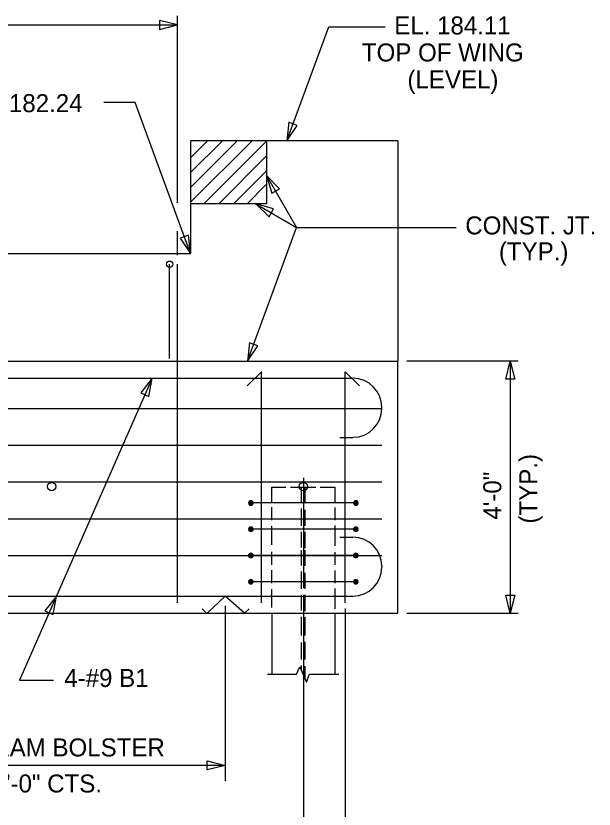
# Model space of a CAD drawing. Extents: x -41 to 251, y -169 to 237.
# Drawn here: x 46.48 to 55.67, y -39.68 to -27.08 of the extents above; entities that cross this region are included whole.
import ezdxf

# ---------------------------------------------------------------- set-up
doc = ezdxf.new("R2010")
doc.units = 0
for name, color, linetype in [('Arrowhead Terminators', 7, 'Continuous'), ('Arrowhead Terminators CELL', 7, 'Continuous'), ('Beam Bolsters CELL', 7, 'Continuous'), ('Dimension Lines', 7, 'Continuous'), ('Mis Object Lines', 7, 'Continuous'), ('Mis Object Lines Hidden', 7, 'Continuous'), ('Rebar Lines', 7, 'Continuous'), ('Rebar Lines CELL', 7, 'Continuous'), ('Sub End Bent Cap Lines CELL', 7, 'Continuous'), ('Text', 7, 'Continuous')]:
    doc.layers.add(name, color=color, linetype=linetype)

# ---------------------------------------------------------------- blocks, each defined once
blk = doc.blocks.new('AH')
at = {"layer": 'Sub End Bent Cap Lines CELL'}
blk.add_lwpolyline([(0, 0), (-1.25, 0.312), (-1.25, -0.312)], close=True, dxfattribs=at)

msp = doc.modelspace()

# ---------------------------------------------------------------- linework, layer by layer
at = {"layer": 'Arrowhead Terminators'}
for points in [[(54.266, -32.851), (54.337, -32.565), (54.409, -32.851)], [(54.409, -36.279), (54.337, -36.565), (54.266, -36.279)]]:
    msp.add_lwpolyline(points, close=True, dxfattribs=at)
at = {"layer": 'Arrowhead Terminators CELL'}
for points in [[(50.786, -29.065), (50.952, -28.821), (50.818, -28.772)], [(50.465, -29.615), (50.546, -29.898), (50.67, -29.827)], [(50.292, -30.065), (50.504, -30.27), (50.575, -30.146)], [(49.257, -30.857), (49.225, -30.564), (49.091, -30.613)], [(50.162, -32.565), (50.328, -32.321), (50.193, -32.272)], [(48.645, -32.836), (48.464, -33.069), (48.595, -33.127)], [(47.124, -36.294), (46.943, -36.528), (47.074, -36.585)], [(49.807, -38.982), (49.521, -39.054), (49.521, -38.911)]]:
    msp.add_lwpolyline(points, close=True, dxfattribs=at)
at = {"layer": 'Beam Bolsters CELL'}
for p, q in [((49.807, -36.294), (49.514, -36.567)), ((50.116, -36.566), (49.807, -36.294)), ((49.514, -36.567), (49.443, -36.496)), ((50.187, -36.495), (50.116, -36.566))]:
    msp.add_line(p, q, dxfattribs=at)
at = {"layer": 'Dimension Lines'}
for p, q in [((49.049, -30.052), (49.049, -27.082)), ((34.049, -27.225), (49.049, -27.225)), ((50.465, -29.615), (50.942, -30.441)), ((50.292, -30.065), (50.942, -30.441)), ((50.942, -30.441), (53.476, -30.441)), ((49.049, -30.881), (49.049, -30.501)), ((54.462, -32.565), (52.692, -32.565)), ((54.337, -32.565), (54.337, -36.565)), ((49.807, -36.446), (49.807, -39.226)), ((51.715, -36.492), (51.715, -41.482)), ((51.049, -36.565), (51.049, -43.982)), ((52.692, -36.565), (54.462, -36.565)), ((49.807, -38.982), (44.001, -38.982))]:
    msp.add_line(p, q, dxfattribs=at)
for points in [[(50.786, -29.065), (51.452, -27.254), (52.347, -27.254)], [(49.257, -30.857), (48.376, -28.459), (47.876, -28.459)], [(50.162, -32.565), (50.942, -30.441)], [(48.645, -32.836), (46.537, -37.627), (47.078, -37.627)]]:
    msp.add_lwpolyline(points, dxfattribs=at)
at = {"layer": 'Mis Object Lines'}
for p, q in [((49.257, -30.041), (50.233, -29.065)), ((49.257, -29.57), (49.762, -29.065)), ((49.257, -29.334), (49.526, -29.065)), ((49.257, -29.065), (49.257, -30.857)), ((49.257, -29.806), (49.997, -29.065)), ((52.549, -29.065), (49.257, -29.065)), ((49.469, -30.065), (50.465, -29.069)), ((50.465, -29.065), (50.465, -30.065)), ((52.549, -29.065), (52.549, -32.565)), ((49.704, -30.065), (50.465, -29.304)), ((49.94, -30.065), (50.465, -29.54)), ((50.155, -30.065), (50.465, -29.755)), ((50.465, -30.065), (49.257, -30.065)), ((40.144, -30.857), (49.257, -30.857)), ((52.549, -36.565), (52.549, -32.565)), ((40.515, -36.565), (52.549, -36.565))]:
    msp.add_line(p, q, dxfattribs=at)
at = {"layer": 'Mis Object Lines Hidden'}
msp.add_line((13.549, -32.565), (52.549, -32.565), dxfattribs=at)
at = {"layer": 'Rebar Lines'}
for p, q in [((48.924, -32.524), (48.924, -31.024)), ((49.049, -36.399), (49.049, -31.024)), ((50.382, -32.732), (50.158, -32.956)), ((50.382, -36.399), (50.382, -32.732)), ((51.715, -36.399), (51.715, -32.732)), ((51.715, -32.732), (51.939, -32.956)), ((14.256, -32.836), (51.836, -32.836)), ((31.836, -33.315), (52.294, -33.315)), ((31.836, -33.899), (52.294, -33.899)), ((31.836, -34.482), (52.294, -34.482)), ((51.049, -34.414), (51.049, -36.17)), ((51.017, -34.808), (51.017, -34.565)), ((51.08, -34.814), (51.08, -34.565)), ((51.017, -35.18), (51.017, -34.901)), ((51.08, -35.18), (51.08, -34.924)), ((31.836, -35.065), (52.294, -35.065)), ((51.017, -35.522), (51.017, -35.273)), ((51.08, -35.534), (51.08, -35.273)), ((51.017, -35.808), (51.017, -35.565)), ((51.08, -35.814), (51.08, -35.565)), ((31.836, -35.649), (52.294, -35.649)), ((51.017, -36.18), (51.017, -35.901)), ((51.08, -36.18), (51.08, -35.924)), ((14.256, -36.294), (51.836, -36.294)), ((51.017, -36.522), (51.017, -36.273)), ((51.049, -36.275), (51.049, -36.565)), ((51.08, -36.534), (51.08, -36.273)), ((50.548, -36.582), (50.548, -37.534)), ((51.017, -36.917), (51.017, -36.621)), ((51.049, -36.635), (51.049, -37.841)), ((51.08, -36.917), (51.08, -36.627)), ((51.549, -36.582), (51.549, -37.534)), ((51.08, -37.301), (51.08, -37.022)), ((51.017, -37.301), (51.017, -37.028)), ((51.017, -37.469), (51.017, -37.394)), ((51.08, -37.618), (51.08, -37.405))]:
    msp.add_line(p, q, dxfattribs=at)
for points in [[(50.548, -34.799), (50.548, -34.565), (50.771, -34.565)], [(50.846, -34.565), (51.246, -34.565)], [(51.315, -34.565), (51.548, -34.565), (51.548, -34.812)], [(50.548, -35.089), (50.548, -34.882)], [(51.548, -34.888), (51.548, -35.086)], [(50.548, -35.477), (50.548, -35.185)], [(51.548, -35.172), (51.548, -35.493)], [(50.548, -35.799), (50.548, -35.591)], [(51.548, -35.597), (51.548, -35.796)], [(50.548, -36.089), (50.548, -35.882)], [(51.548, -35.888), (51.548, -36.086)], [(50.548, -36.477), (50.548, -36.185)], [(51.548, -36.172), (51.548, -36.493)], [(50.479, -37.535), (50.94, -37.535), (50.995, -37.415), (51.097, -37.66), (51.149, -37.535), (51.615, -37.535)]]:
    msp.add_lwpolyline(points, dxfattribs=at)
for centre, radius in [((48.924, -31.024), 0.0495), ((47.049, -34.554), 0.066), ((51.049, -34.554), 0.066)]:
    msp.add_circle(centre, radius, dxfattribs=at)
at = {"layer": 'Rebar Lines CELL'}
for p, q in [((52.294, -33.315), (52.294, -33.294)), ((51.628, -33.774), (51.836, -33.774)), ((51.882, -34.815), (50.215, -34.815)), ((51.882, -35.232), (50.215, -35.232)), ((51.628, -35.357), (51.836, -35.357)), ((51.882, -35.649), (50.215, -35.649)), ((52.294, -35.815), (52.294, -35.836)), ((51.882, -36.065), (50.215, -36.065))]:
    msp.add_line(p, q, dxfattribs=at)
for points in [[(50.215, -34.78), (50.202, -34.783), (50.19, -34.79), (50.183, -34.802), (50.18, -34.815), (50.183, -34.829), (50.19, -34.84), (50.202, -34.848), (50.215, -34.851), (50.229, -34.848), (50.24, -34.84), (50.248, -34.829), (50.25, -34.815), (50.248, -34.802), (50.24, -34.79), (50.229, -34.783), (50.215, -34.78), (50.215, -34.815), (50.215, -34.851), (50.202, -34.848), (50.215, -34.815), (50.19, -34.84), (50.183, -34.829), (50.215, -34.815), (50.18, -34.815), (50.183, -34.802), (50.215, -34.815), (50.19, -34.79), (50.202, -34.783), (50.215, -34.815), (50.229, -34.783), (50.24, -34.79), (50.215, -34.815), (50.248, -34.802), (50.25, -34.815), (50.215, -34.815), (50.248, -34.829), (50.24, -34.84), (50.215, -34.815), (50.229, -34.848)], [(51.882, -34.78), (51.868, -34.783), (51.857, -34.79), (51.849, -34.802), (51.847, -34.815), (51.849, -34.829), (51.857, -34.84), (51.868, -34.848), (51.882, -34.851), (51.895, -34.848), (51.907, -34.84), (51.914, -34.829), (51.917, -34.815), (51.914, -34.802), (51.907, -34.79), (51.895, -34.783), (51.882, -34.78), (51.882, -34.815), (51.882, -34.851), (51.868, -34.848), (51.882, -34.815), (51.857, -34.84), (51.849, -34.829), (51.882, -34.815), (51.847, -34.815), (51.849, -34.802), (51.882, -34.815), (51.857, -34.79), (51.868, -34.783), (51.882, -34.815), (51.895, -34.783), (51.907, -34.79), (51.882, -34.815), (51.914, -34.802), (51.917, -34.815), (51.882, -34.815), (51.914, -34.829), (51.907, -34.84), (51.882, -34.815), (51.895, -34.848)], [(50.215, -35.197), (50.202, -35.199), (50.19, -35.207), (50.183, -35.218), (50.18, -35.232), (50.183, -35.245), (50.19, -35.257), (50.202, -35.264), (50.215, -35.267), (50.229, -35.264), (50.24, -35.257), (50.248, -35.245), (50.25, -35.232), (50.248, -35.218), (50.24, -35.207), (50.229, -35.199), (50.215, -35.197), (50.215, -35.232), (50.215, -35.267), (50.202, -35.264), (50.215, -35.232), (50.19, -35.257), (50.183, -35.245), (50.215, -35.232), (50.18, -35.232), (50.183, -35.218), (50.215, -35.232), (50.19, -35.207), (50.202, -35.199), (50.215, -35.232), (50.229, -35.199), (50.24, -35.207), (50.215, -35.232), (50.248, -35.218), (50.25, -35.232), (50.215, -35.232), (50.248, -35.245), (50.24, -35.257), (50.215, -35.232), (50.229, -35.264)], [(51.882, -35.197), (51.868, -35.199), (51.857, -35.207), (51.849, -35.218), (51.847, -35.232), (51.849, -35.245), (51.857, -35.257), (51.868, -35.264), (51.882, -35.267), (51.895, -35.264), (51.907, -35.257), (51.914, -35.245), (51.917, -35.232), (51.914, -35.218), (51.907, -35.207), (51.895, -35.199), (51.882, -35.197), (51.882, -35.232), (51.882, -35.267), (51.868, -35.264), (51.882, -35.232), (51.857, -35.257), (51.849, -35.245), (51.882, -35.232), (51.847, -35.232), (51.849, -35.218), (51.882, -35.232), (51.857, -35.207), (51.868, -35.199), (51.882, -35.232), (51.895, -35.199), (51.907, -35.207), (51.882, -35.232), (51.914, -35.218), (51.917, -35.232), (51.882, -35.232), (51.914, -35.245), (51.907, -35.257), (51.882, -35.232), (51.895, -35.264)], [(50.215, -35.613), (50.202, -35.616), (50.19, -35.624), (50.183, -35.635), (50.18, -35.649), (50.183, -35.662), (50.19, -35.674), (50.202, -35.681), (50.215, -35.684), (50.229, -35.681), (50.24, -35.674), (50.248, -35.662), (50.25, -35.649), (50.248, -35.635), (50.24, -35.624), (50.229, -35.616), (50.215, -35.613), (50.215, -35.649), (50.215, -35.684), (50.202, -35.681), (50.215, -35.649), (50.19, -35.674), (50.183, -35.662), (50.215, -35.649), (50.18, -35.649), (50.183, -35.635), (50.215, -35.649), (50.19, -35.624), (50.202, -35.616), (50.215, -35.649), (50.229, -35.616), (50.24, -35.624), (50.215, -35.649), (50.248, -35.635), (50.25, -35.649), (50.215, -35.649), (50.248, -35.662), (50.24, -35.674), (50.215, -35.649), (50.229, -35.681)], [(51.882, -35.613), (51.868, -35.616), (51.857, -35.624), (51.849, -35.635), (51.847, -35.649), (51.849, -35.662), (51.857, -35.674), (51.868, -35.681), (51.882, -35.684), (51.895, -35.681), (51.907, -35.674), (51.914, -35.662), (51.917, -35.649), (51.914, -35.635), (51.907, -35.624), (51.895, -35.616), (51.882, -35.613), (51.882, -35.649), (51.882, -35.684), (51.868, -35.681), (51.882, -35.649), (51.857, -35.674), (51.849, -35.662), (51.882, -35.649), (51.847, -35.649), (51.849, -35.635), (51.882, -35.649), (51.857, -35.624), (51.868, -35.616), (51.882, -35.649), (51.895, -35.616), (51.907, -35.624), (51.882, -35.649), (51.914, -35.635), (51.917, -35.649), (51.882, -35.649), (51.914, -35.662), (51.907, -35.674), (51.882, -35.649), (51.895, -35.681)], [(50.215, -36.03), (50.202, -36.033), (50.19, -36.04), (50.183, -36.052), (50.18, -36.065), (50.183, -36.079), (50.19, -36.09), (50.202, -36.098), (50.215, -36.101), (50.229, -36.098), (50.24, -36.09), (50.248, -36.079), (50.25, -36.065), (50.248, -36.052), (50.24, -36.04), (50.229, -36.033), (50.215, -36.03), (50.215, -36.065), (50.215, -36.101), (50.202, -36.098), (50.215, -36.065), (50.19, -36.09), (50.183, -36.079), (50.215, -36.065), (50.18, -36.065), (50.183, -36.052), (50.215, -36.065), (50.19, -36.04), (50.202, -36.033), (50.215, -36.065), (50.229, -36.033), (50.24, -36.04), (50.215, -36.065), (50.248, -36.052), (50.25, -36.065), (50.215, -36.065), (50.248, -36.079), (50.24, -36.09), (50.215, -36.065), (50.229, -36.098)], [(51.882, -36.03), (51.868, -36.033), (51.857, -36.04), (51.849, -36.052), (51.847, -36.065), (51.849, -36.079), (51.857, -36.09), (51.868, -36.098), (51.882, -36.101), (51.895, -36.098), (51.907, -36.09), (51.914, -36.079), (51.917, -36.065), (51.914, -36.052), (51.907, -36.04), (51.895, -36.033), (51.882, -36.03), (51.882, -36.065), (51.882, -36.101), (51.868, -36.098), (51.882, -36.065), (51.857, -36.09), (51.849, -36.079), (51.882, -36.065), (51.847, -36.065), (51.849, -36.052), (51.882, -36.065), (51.857, -36.04), (51.868, -36.033), (51.882, -36.065), (51.895, -36.033), (51.907, -36.04), (51.882, -36.065), (51.914, -36.052), (51.917, -36.065), (51.882, -36.065), (51.914, -36.079), (51.907, -36.09), (51.882, -36.065), (51.895, -36.098)]]:
    msp.add_lwpolyline(points, dxfattribs=at)
for centre, start, end in [((51.836, -33.294), 0, 90), ((51.836, -33.315), 270, 0), ((51.836, -35.815), 0, 90), ((51.836, -35.836), 270, 0)]:
    msp.add_arc(centre, 0.458, start, end, dxfattribs=at)
at = {"layer": 'Text'}
msp.add_line((52.549, -36.565), (52.549, -36.565), dxfattribs=at)

# ---------------------------------------------------------------- block references
at = {"layer": 'Arrowhead Terminators CELL', "xscale": 0.2288, "yscale": 0.2288}
msp.add_blockref('AH', (49.049, -27.225), dxfattribs=at)

# ---------------------------------------------------------------- texts
at = {"layer": 'Text'}
for s, p in [('EL. 184.11', (52.493, -27.377)), ('TOP OF WING', (51.979, -27.806)), ('(LEVEL)', (52.703, -28.235)), ('EL. 182.24', (45.69, -28.611)), ('CONST. JT.', (53.622, -30.552)), ('(TYP.)', (54.156, -30.963)), ('4-#9 B1', (47.25, -37.736)), ('3" HIGH BEAM BOLSTER', (44.355, -38.839)), ('@ 5\'-0" CTS.', (45.616, -39.411))]:
    msp.add_text(s, height=0.286, dxfattribs=at).set_placement(p)
for s, p in [('(TYP.)', (54.766, -35.142)), ('4\'-0"', (54.194, -35.08))]:
    msp.add_text(s, height=0.286, rotation=90, dxfattribs=at).set_placement(p)

doc.saveas('drawing.dxf')
